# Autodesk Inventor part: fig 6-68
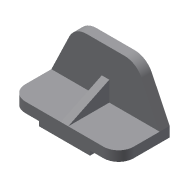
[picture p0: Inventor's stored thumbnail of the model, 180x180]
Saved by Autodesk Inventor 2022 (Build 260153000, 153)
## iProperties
Created: 2001-12
Part Number: fig 6-68
Document SubType Name: Modeling
Designer: Renu Muthoo
Density: 1 g/cm^3
Material: Generic
Appearance: Default
Control State: 0
Master: False
Checked Out: False
Shininess: 77.0
Length Units: 11269
Angle Units: 11279
Time Units: 11290
Mass Units: 11283
Length Display Precision: 3
Angle Display Precision: 2
Density: 0.0
Volumn: 0.0
Area: 0.0
PropertySet Name: Model Information
Author: Renu Muthoo
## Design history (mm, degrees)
node "Sketch1"
sketch "Sketch2"
  geometry: L1 (-67.219, 19.116)-(148.781, 19.116); L2 (148.781, 19.116)-(148.781, -0.884); L3 (-67.219, -0.884)-(-67.219, 19.116); L4 (-10.219, -0.884)-(-10.219, -9.884); L5 (-10.219, -9.884)-(91.781, -9.884); L6 (91.781, -9.884)-(91.781, -0.884); L7 (148.781, -0.884)-(91.781, -0.884); L8 (-10.219, -0.884)-(-67.219, -0.884)
  constraints: 16 end point, 5 parallel, 4 perpendicular, 2 equal length, 1 horizontal
  dimensions: "d0" = 102 distance of L4.end L5.end; "d1" = 57 distance of L4.start L3.start; "d2" = 29 distance between parallel lines of L1 L5; "d3" = 20 distance of L1.end L2.end
extrude "Extrusion1" new body sketch "Sketch2" distance "d4" = 102; taper "d5" = 0 deg
sketch "Sketch3"
  geometry: L1 (67.219, -19.116)-(-148.781, -19.116) reference; L2 (67.219, -19.116)-(31.475, -93.564); L3 (-2.781, -115.116)-(-78.781, -115.116); L4 (-113.038, -93.564)-(-148.781, -19.116); A1 r 38 centre (-2.781, -77.116) between (-2.781, -115.116) and (31.475, -93.564); A2 r 38 centre (-78.781, -77.116) between (-113.038, -93.564) and (-78.781, -115.116)
  constraints: 6 end point, 4 point on circle, 4 tangent, 2 centre point, 1 equal length, 1 equal radius, 1 parallel
  dimensions: "d6" = 96 distance between parallel lines of L3 L1; "d7" = 38 radius of A1; "d8" = 76 distance of A2.centre A1.centre
extrude "Extrusion2" join sketch "Sketch3" distance "d9" = 20; taper "d10" = 0 deg
fillet "Fillet1" dims "d11" = 30
workplane "Work Plane1"
sketch "Sketch7"
  geometry: L1 (0, -82)-(-39.557, 0)
  constraints: 2 end point
feature "Rib4" sketch "Sketch7" dims "d37" = 1, "d38" = 15, "d39" = 0
body "Solid1"
other parameters: "d12" = -108
